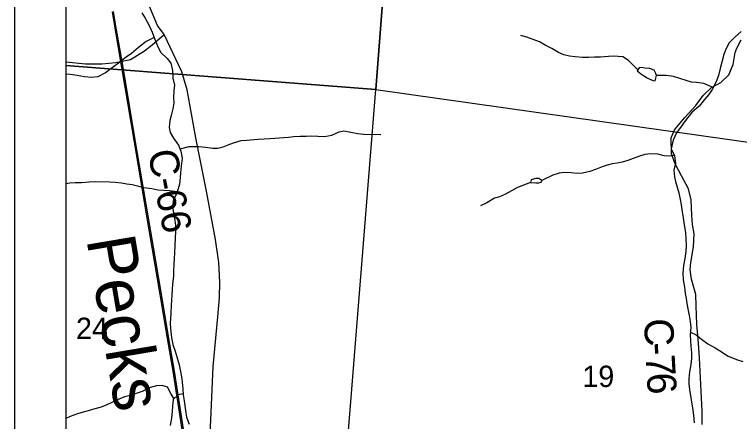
# Model space of a CAD drawing. Extents: x 0 to 40.8, y 0 to 22.
# Drawn here: x 2 to 3.414, y 19.735 to 20.53 of the extents above; entities that cross this region are included whole.
import ezdxf

# ---------------------------------------------------------------- set-up
doc = ezdxf.new("R2010")
doc.units = 0
for name, color, linetype in [('Default', 7, 'Continuous'), ('GM_X_County_Road', 7, 'Continuous'), ('GM_X_County_Road_Text', 7, 'Continuous'), ('GM_X_Minor_Lake', 7, 'Continuous'), ('GM_X_Minor_River', 7, 'Continuous'), ('GM_X_Minor_River_Text', 7, 'Continuous'), ('GM_X_Rail_Line', 7, 'Continuous'), ('GM_X_Section', 7, 'Continuous'), ('GM_X_Section_Text', 7, 'Continuous'), ('GM_X_Township_Road', 7, 'Continuous'), ('SH_Cut_Line', 7, 'Continuous'), ('SH_Data', 7, 'Continuous')]:
    doc.layers.add(name, color=color, linetype=linetype)

msp = doc.modelspace()

# ---------------------------------------------------------------- linework, layer by layer
at = {"layer": 'Default'}
msp.add_lwpolyline([(3.6829, 20.9), (2.1, 20.9), (2.1, 17.4153), (2.4594, 17.3966), (2.8463, 17.3693), (2.8484, 17.3691), (3.1244, 17.3534), (3.4481, 17.3334), (3.5638, 19.132), (3.5742, 19.2945), (3.575, 19.3064), (3.6386, 20.2396), (3.6672, 20.5588), (3.6703, 20.6733)], close=True, dxfattribs=at)
at = {"layer": 'GM_X_County_Road'}
for points in [[(2.7446, 20.9), (2.1, 20.9), (2.1, 20.4303), (2.7045, 20.3832)], [(3.6903, 20.9), (2.7446, 20.9), (2.7045, 20.3832), (3.6475, 20.2502)], [(2.1, 20.4303), (2.1, 19.4381), (2.6264, 19.4085), (2.7045, 20.3832)]]:
    msp.add_lwpolyline(points, close=True, dxfattribs=at)
for points in [[(2.3818, 19.713), (2.3826, 19.7381), (2.3877, 19.8425), (2.3966, 19.9394), (2.3998, 19.9766), (2.4007, 20.007), (2.3986, 20.0454), (2.392, 20.0903), (2.3747, 20.1851), (2.3539, 20.2889), (2.3451, 20.3357), (2.3366, 20.3829), (2.3261, 20.4179), (2.2916, 20.4907), (2.279, 20.5082), (2.2602, 20.5531)], [(3.341, 19.7294), (3.3414, 19.7557), (3.3358, 19.8595), (3.3336, 19.8964), (3.3305, 19.9247), (3.3294, 19.9613), (3.3287, 19.9829), (3.3206, 20.0132), (3.3175, 20.0314), (3.319, 20.0456), (3.3243, 20.076), (3.3254, 20.1018), (3.322, 20.1197), (3.3211, 20.138), (3.3195, 20.1681), (3.3144, 20.1893), (3.3007, 20.215), (3.2881, 20.2383), (3.281, 20.2579), (3.2807, 20.289), (3.2874, 20.3045), (3.3068, 20.3277), (3.3289, 20.3523), (3.343, 20.3716), (3.359, 20.3875), (3.3774, 20.3968), (3.393, 20.412), (3.4014, 20.432), (3.4052, 20.4553), (3.4084, 20.464), (3.4169, 20.4805)]]:
    msp.add_lwpolyline(points, dxfattribs=at)
at = {"layer": 'GM_X_Minor_Lake'}
for points in [[(3.2523, 20.4107), (3.2509, 20.4146), (3.2476, 20.4211), (3.2389, 20.4243), (3.2295, 20.4248), (3.2219, 20.4265), (3.2185, 20.4258), (3.2142, 20.4195), (3.2209, 20.4148), (3.2269, 20.4109), (3.234, 20.4058), (3.24, 20.403), (3.2453, 20.4006), (3.2495, 20.4005)], [(3.2495, 20.4005), (3.2523, 20.4107)], [(3.0225, 20.2095), (3.0168, 20.2093), (3.0095, 20.2075), (3.0076, 20.2068), (3.0064, 20.2019), (3.0166, 20.2009), (3.0223, 20.2012), (3.0269, 20.2022), (3.0285, 20.2056)], [(3.0285, 20.2056), (3.0225, 20.2095)]]:
    msp.add_lwpolyline(points, dxfattribs=at)
at = {"layer": 'GM_X_Minor_River'}
for points in [[(2.248, 20.533), (2.2547, 20.5227), (2.2627, 20.5081), (2.2685, 20.4951), (2.2728, 20.4828), (2.279, 20.4683), (2.2848, 20.456), (2.2975, 20.444), (2.3049, 20.4344), (2.308, 20.4203), (2.3089, 20.4054), (2.312, 20.3917), (2.3107, 20.3819), (2.3104, 20.3667), (2.311, 20.3572), (2.3089, 20.3455), (2.3056, 20.3326), (2.3031, 20.3228), (2.3017, 20.3092), (2.3038, 20.2993), (2.31, 20.2881), (2.32, 20.2746), (2.3247, 20.2628), (2.3267, 20.2491), (2.3253, 20.2339), (2.3239, 20.2207), (2.323, 20.2108), (2.3216, 20.1983), (2.3175, 20.1828), (2.3092, 20.1652), (2.3082, 20.1549), (2.3103, 20.142), (2.3123, 20.1313), (2.314, 20.1184), (2.3141, 20.1062), (2.3135, 20.0933), (2.3118, 20.0649), (2.3112, 20.0524), (2.311, 20.0421), (2.3104, 20.0293), (2.3098, 20.019), (2.308, 20.0039), (2.3074, 19.9925), (2.3068, 19.9826), (2.3062, 19.972), (2.3056, 19.9618), (2.305, 19.9474), (2.3038, 19.9261), (2.3046, 19.9102), (2.3059, 19.8988), (2.3091, 19.8858), (2.3134, 19.8724), (2.318, 19.8572), (2.3212, 19.8461), (2.324, 19.8331), (2.3257, 19.8228), (2.327, 19.8118), (2.3283, 19.7985), (2.3292, 19.7871), (2.3309, 19.7757), (2.3335, 19.7566), (2.3352, 19.7441), (2.3406, 19.7303)], [(3.2158, 20.4219), (3.1975, 20.4399), (3.1863, 20.447), (3.1681, 20.4485), (3.1583, 20.4479), (3.1427, 20.4467), (3.1313, 20.4465), (3.1192, 20.446), (3.1085, 20.4458), (3.0934, 20.4469), (3.0821, 20.4483), (3.0715, 20.4511), (3.061, 20.4555), (3.0478, 20.4634), (3.0351, 20.4697), (3.0238, 20.476), (3.0114, 20.4812), (2.999, 20.4856), (2.9877, 20.4885)], [(3.417, 20.4967), (3.4039, 20.4848), (3.3938, 20.4744), (3.3872, 20.4623), (3.3832, 20.4514), (3.3795, 20.4367), (3.3762, 20.4242), (3.3729, 20.4103), (3.3677, 20.3971), (3.3606, 20.3835), (3.3544, 20.3738), (3.3455, 20.3637), (3.335, 20.3507), (3.3211, 20.3384), (3.3082, 20.3219), (3.3001, 20.3111), (3.2911, 20.2984), (3.2844, 20.2845), (3.2807, 20.2675), (3.2868, 20.2537), (3.2888, 20.2396), (3.2855, 20.226), (3.2868, 20.2131), (3.2893, 20.2035), (3.2921, 20.1928), (3.2957, 20.1818), (3.2981, 20.1688), (3.3002, 20.1581), (3.3022, 20.1444), (3.3038, 20.1326), (3.3062, 20.1189), (3.3086, 20.1041), (3.3095, 20.0927), (3.31, 20.0779), (3.309, 20.0669), (3.3072, 20.0532), (3.3047, 20.04), (3.3033, 20.0248), (3.3042, 20.0115), (3.3065, 19.9978), (3.3082, 19.9853), (3.3099, 19.9754), (3.3112, 19.9659), (3.3136, 19.9518), (3.3157, 19.9419), (3.3178, 19.9304), (3.3187, 19.9186), (3.318, 19.9046), (3.3182, 19.8925), (3.3191, 19.8826), (3.3204, 19.8693), (3.3202, 19.8583), (3.3188, 19.8465), (3.3162, 19.8325), (3.3149, 19.8193), (3.3154, 19.809), (3.3167, 19.7976), (3.3191, 19.7812), (3.3211, 19.7698), (3.3228, 19.7576), (3.3245, 19.7477), (3.3257, 19.7329)], [(2.2721, 20.4849), (2.2568, 20.4771), (2.2418, 20.4652), (2.2283, 20.4537), (2.2175, 20.4463), (2.2029, 20.4345), (2.1906, 20.4256), (2.1775, 20.416), (2.1626, 20.4083), (2.1504, 20.407), (2.1368, 20.4081), (2.1221, 20.4103), (2.1088, 20.4124), (2.1, 20.4135)], [(3.3624, 20.387), (3.3445, 20.3952), (3.3302, 20.3967), (3.3203, 20.3976), (3.3101, 20.4009), (3.2973, 20.4049), (3.2849, 20.4086), (3.2709, 20.4107), (3.2523, 20.4107)], [(2.323, 20.2672), (2.3404, 20.272), (2.3503, 20.2722), (2.3598, 20.272), (2.3726, 20.271), (2.3866, 20.2688), (2.3965, 20.269), (2.4068, 20.2714), (2.4167, 20.2754), (2.4274, 20.2794), (2.4419, 20.2836), (2.4525, 20.2846), (2.4753, 20.2864), (2.4871, 20.2869), (2.4981, 20.2875), (2.5076, 20.2884), (2.5342, 20.2905), (2.5448, 20.2915), (2.5573, 20.2924), (2.5687, 20.2925), (2.5793, 20.2927), (2.5915, 20.2921), (2.6047, 20.2918), (2.6188, 20.2942), (2.6329, 20.3007), (2.6425, 20.3028), (2.6561, 20.2999), (2.6697, 20.2974), (2.6814, 20.296), (2.7147, 20.2953)], [(3.2865, 20.2545), (3.2777, 20.2535), (3.2671, 20.2537), (3.2543, 20.257), (3.2407, 20.258), (3.2293, 20.2563), (3.2186, 20.2531), (3.2064, 20.2484), (3.196, 20.2448), (3.185, 20.2416), (3.1755, 20.2395), (3.1656, 20.2382), (3.1561, 20.2354), (3.1458, 20.2325), (3.1328, 20.2271), (3.1217, 20.2235), (3.1076, 20.22), (3.0981, 20.2194), (3.0853, 20.2208), (3.0724, 20.2215), (3.0625, 20.2198), (3.0499, 20.2162), (3.0285, 20.2056)], [(2.3177, 20.1837), (2.3024, 20.1854), (2.291, 20.1864), (2.2793, 20.187), (2.2676, 20.1891), (2.2524, 20.1917), (2.2423, 20.1942), (2.2294, 20.1971), (2.2192, 20.1988), (2.2086, 20.2002), (2.1965, 20.2019), (2.1852, 20.2025), (2.1579, 20.2031), (2.1454, 20.2026), (2.1305, 20.2013), (2.118, 20.2012), (2.1078, 20.2006), (2.1, 20.1993)], [(3.0064, 20.2019), (2.9808, 20.1921), (2.9693, 20.1852), (2.9574, 20.1793), (2.9456, 20.1739), (2.936, 20.171), (2.9211, 20.1618), (2.9085, 20.156)], [(3.3183, 19.91), (3.3294, 19.9044), (3.3395, 19.8962), (3.3522, 19.8869), (3.3664, 19.879), (3.3803, 19.8704), (3.3904, 19.8637), (3.4081, 19.8561), (3.4201, 19.8525)], [(2.3109, 19.7799), (2.3046, 19.7899), (2.2984, 19.8021), (2.2878, 19.8058), (2.2768, 19.8052), (2.2643, 19.8017), (2.2489, 19.794), (2.2394, 19.7904), (2.226, 19.7861), (2.2146, 19.7833), (2.2009, 19.7775), (2.1901, 19.7724), (2.1798, 19.768), (2.1691, 19.7633), (2.1565, 19.7598), (2.1436, 19.7562), (2.1337, 19.7538), (2.1226, 19.7506), (2.1085, 19.7451), (2.1, 19.7412)], [(2.329, 19.7892), (2.319, 19.7877), (2.3093, 19.7784), (2.3083, 19.7651), (2.3077, 19.7556), (2.3063, 19.7416), (2.3038, 19.7272)]]:
    msp.add_lwpolyline(points, dxfattribs=at)
at = {"layer": 'GM_X_Rail_Line'}
for points in [[(2.513, 18.6034), (2.4911, 18.7253), (2.4637, 18.8795), (2.4436, 18.9921), (2.4302, 19.0682), (2.4185, 19.136), (2.4069, 19.2045), (2.3933, 19.2876), (2.3823, 19.3597), (2.3722, 19.4258), (2.3592, 19.51), (2.3464, 19.5941), (2.3273, 19.7197), (2.3094, 19.8333), (2.2974, 19.9049), (2.2843, 19.9833), (2.2581, 20.1363), (2.2331, 20.2846), (2.2093, 20.4264), (2.1948, 20.5107), (2.1908, 20.5348)], [(2.5154, 18.6038), (2.4935, 18.7257), (2.4661, 18.8799), (2.446, 18.9926), (2.4326, 19.0686), (2.4208, 19.1364), (2.4093, 19.2049), (2.3957, 19.2879), (2.3846, 19.3601), (2.3746, 19.4262), (2.3616, 19.5103), (2.3488, 19.5945), (2.3297, 19.7201), (2.3118, 19.8337), (2.2998, 19.9053), (2.2866, 19.9837), (2.2605, 20.1367), (2.2355, 20.285), (2.2117, 20.4268), (2.1972, 20.5111), (2.1932, 20.5352)]]:
    msp.add_lwpolyline(points, dxfattribs=at)
at = {"layer": 'GM_X_Section'}
msp.add_lwpolyline([(2.7045, 20.3832), (3.6475, 20.2502), (3.5805, 19.3077), (2.6264, 19.4085)], close=True, dxfattribs=at)
at = {"layer": 'GM_X_Township_Road'}
msp.add_lwpolyline([(2.1, 20.4374), (2.1387, 20.4334), (2.1705, 20.4332), (2.1979, 20.4361), (2.226, 20.4417), (2.2534, 20.459), (2.2683, 20.4707), (2.2916, 20.4907)], dxfattribs=at)
at = {"layer": 'SH_Cut_Line'}
msp.add_lwpolyline([(7.7204, 20.9), (2.1, 20.9), (2.1, 17.4153), (2.4594, 17.3966), (2.8463, 17.3693), (2.8484, 17.3691), (3.1244, 17.3534), (3.4481, 17.3334), (4.5348, 17.2687), (4.8294, 17.2493), (5.3407, 17.2146), (5.6278, 17.197), (6.1785, 17.166), (6.9172, 17.1197), (7.4495, 17.0841), (7.4798, 17.5479), (7.4963, 17.9476), (7.5246, 18.2047), (7.5789, 18.8336), (7.595, 19.0259), (7.6007, 19.1025), (7.6007, 19.1071), (7.6192, 19.376), (7.7055, 20.511)], close=True, dxfattribs=at)
at = {"layer": 'SH_Data'}
for p, q in [((2, 21), (2, 14)), ((2.1, 20.9), (2.1, 14.1))]:
    msp.add_line(p, q, dxfattribs=at)

# ---------------------------------------------------------------- texts
at = {"layer": 'GM_X_County_Road_Text'}
for s, height, rotation, p in [('C-66', 0.05682, 281.0403, (2.2597, 20.2611)), ('C', 0.0568, 271.9284, (3.2279, 19.9359)), ('-', 0.0568, 272.5119, (3.2295, 19.8887)), ('7', 0.0568, 273.185, (3.2306, 19.8646)), ('6', 0.0568, 273.983, (3.2326, 19.8288))]:
    msp.add_text(s, height=height, rotation=rotation, dxfattribs=at).set_placement(p)
at = {"layer": 'GM_X_Minor_River_Text'}
msp.add_text('Pecks', height=0.09471, rotation=279.605, dxfattribs=at).set_placement((2.1401, 20.0909))
at = {"layer": 'GM_X_Section_Text'}
for s, p in [('24', (2.1199, 19.8962)), ('19', (3.1074, 19.8025))]:
    msp.add_text(s, height=0.04186, rotation=0, dxfattribs=at).set_placement(p)

doc.saveas('drawing.dxf')
